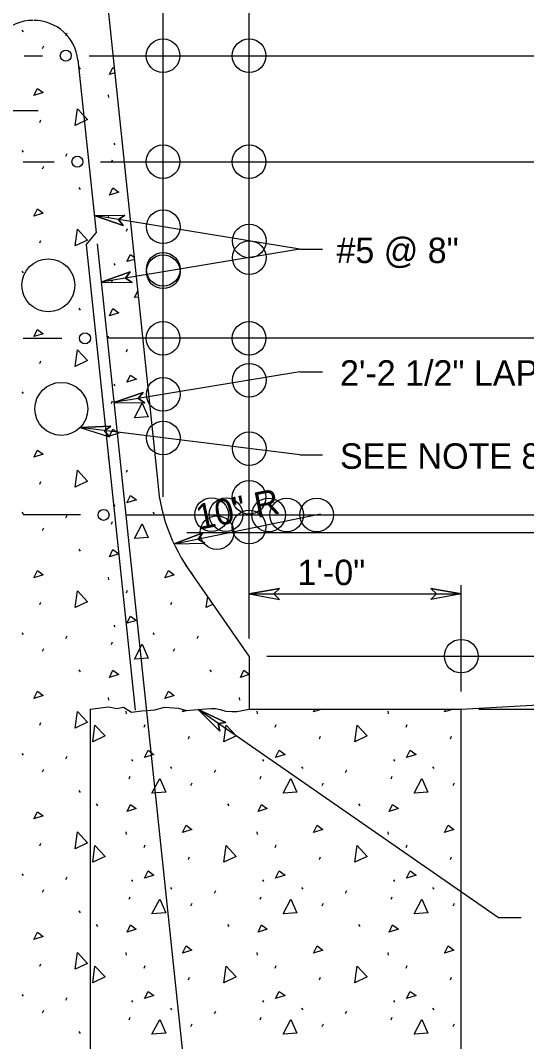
# Model space of a CAD drawing. Extents: x -26.5 to -19.2, y -3.6 to 6.6.
# Drawn here: x -23.277 to -22.083, y 2.961 to 5.371 of the extents above; entities that cross this region are included whole.
import ezdxf

# ---------------------------------------------------------------- set-up
doc = ezdxf.new("R2010")
doc.units = 0
for name, color, linetype in [('ANNO-WOUT', 7, 'Continuous'), ('CABLE_RUN', 7, 'Continuous'), ('DETL-DIMS', 7, 'Continuous'), ('DETL-PATT', 7, 'Continuous'), ('Level 10', 7, 'Continuous'), ('Level 12', 7, 'Continuous'), ('SECT-GRND_P', 7, 'Continuous'), ('SUBS-FOOT_P', 7, 'Continuous'), ('SUPR-PARA_P', 7, 'Continuous'), ('SUPR-RFRC', 7, 'Continuous')]:
    doc.layers.add(name, color=color, linetype=linetype)

msp = doc.modelspace()

# ---------------------------------------------------------------- linework, layer by layer
at = {"layer": 'ANNO-WOUT'}
for centre in [(-22.9404, 5.2872), (-22.7373, 5.2872), (-22.9404, 5.0372), (-22.7373, 5.0372), (-22.9401, 4.8836), (-22.737, 4.8501), (-22.737, 4.8109), (-22.9401, 4.7833), (-22.9401, 4.7774), (-22.9404, 4.6205), (-22.7373, 4.6205), (-22.737, 4.5216), (-22.9401, 4.4881), (-22.9401, 4.3853), (-22.737, 4.36), (-22.7373, 4.2454), (-22.826, 4.2044), (-22.7919, 4.2044), (-22.6912, 4.2039), (-22.6488, 4.2039), (-22.578, 4.2039), (-22.8133, 4.1622), (-22.7373, 4.1751), (-22.237, 3.8705)]:
    msp.add_circle(centre, 0.0397, dxfattribs=at)
at = {"layer": 'CABLE_RUN'}
for centre in [(-23.2111, 4.7455), (-23.1804, 4.4539)]:
    msp.add_circle(centre, 0.0625, dxfattribs=at)
at = {"layer": 'DETL-DIMS'}
for p, q in [((-23.1028, 4.9104), (-23.0302, 4.9113)), ((-23.1028, 4.9104), (-23.0343, 4.8864)), ((-23.0456, 4.901), (-23.0302, 4.9113)), ((-23.0343, 4.8864), (-23.0456, 4.901)), ((-23.0862, 4.7533), (-23.0177, 4.7773)), ((-23.0177, 4.7773), (-23.029, 4.7627)), ((-23.0862, 4.7533), (-23.0136, 4.7524)), ((-23.029, 4.7627), (-23.0136, 4.7524)), ((-23.0563, 4.469), (-22.9877, 4.4929)), ((-22.9877, 4.4929), (-22.999, 4.4784)), ((-23.0563, 4.469), (-22.9836, 4.4681)), ((-22.999, 4.4784), (-22.9836, 4.4681)), ((-23.1362, 4.4097), (-23.0637, 4.4133)), ((-23.1362, 4.4097), (-23.0668, 4.3883)), ((-23.0637, 4.4133), (-23.0786, 4.4025)), ((-23.0786, 4.4025), (-23.0668, 4.3883)), ((-22.9141, 4.1352), (-22.8465, 4.1617)), ((-22.8465, 4.1617), (-22.8572, 4.1468)), ((-22.8572, 4.1468), (-22.8415, 4.137)), ((-22.9141, 4.1352), (-22.8415, 4.137)), ((-22.737, 4.0173), (-22.6655, 4.0298)), ((-22.6655, 4.0298), (-22.679, 4.0173)), ((-22.237, 4.0173), (-22.3085, 4.0298)), ((-22.3085, 4.0298), (-22.295, 4.0173)), ((-22.737, 4.0173), (-22.6655, 4.0046)), ((-22.679, 4.0173), (-22.6655, 4.0046)), ((-22.237, 4.0173), (-22.3085, 4.0046)), ((-22.295, 4.0173), (-22.3085, 4.0046)), ((-22.8579, 3.7446), (-22.792, 3.7142)), ((-22.8579, 3.7446), (-22.8064, 3.6935)), ((-22.792, 3.7142), (-22.8102, 3.7116)), ((-22.8102, 3.7116), (-22.8064, 3.6935))]:
    msp.add_line(p, q, dxfattribs=at)
for points in [[(-23.0343, 4.8864), (-23.1028, 4.9104), (-23.0302, 4.9113), (-23.0456, 4.901)], [(-23.0177, 4.7773), (-23.0862, 4.7533), (-23.0136, 4.7524), (-23.029, 4.7627)], [(-22.9877, 4.4929), (-23.0563, 4.469), (-22.9836, 4.4681), (-22.999, 4.4784)], [(-23.0637, 4.4133), (-23.1362, 4.4097), (-23.0668, 4.3883), (-23.0786, 4.4025)], [(-22.8465, 4.1617), (-22.9141, 4.1352), (-22.8415, 4.137), (-22.8572, 4.1468)], [(-22.6655, 4.0298), (-22.737, 4.0173), (-22.6655, 4.0046), (-22.679, 4.0173)], [(-22.3085, 4.0298), (-22.237, 4.0173), (-22.3085, 4.0046), (-22.295, 4.0173)], [(-22.792, 3.7142), (-22.8579, 3.7446), (-22.8064, 3.6935), (-22.8102, 3.7116)]]:
    msp.add_lwpolyline(points, close=True, dxfattribs=at)
at = {"layer": 'DETL-PATT'}
for p, q in [((-23.2737, 5.3478), (-23.2707, 5.344)), ((-23.1694, 5.3347), (-23.1663, 5.3409)), ((-23.225, 5.3045), (-23.222, 5.3107)), ((-23.1393, 5.2605), (-23.1362, 5.2559)), ((-23.0545, 5.2466), (-23.0666, 5.2427)), ((-23.0697, 5.1948), (-23.0689, 5.1886)), ((-23.2312, 5.1299), (-23.2289, 5.136)), ((-23.2737, 5.0634), (-23.2707, 5.0595)), ((-23.0565, 5.0812), (-23.0542, 5.0773)), ((-23.1694, 5.0502), (-23.1663, 5.0564)), ((-23.062, 5.0356), (-23.0596, 5.0417)), ((-23.225, 5.0201), (-23.222, 5.0263)), ((-23.1393, 4.976), (-23.1362, 4.9714)), ((-23.0697, 4.9103), (-23.0689, 4.9042)), ((-23.0264, 4.8732), (-23.0241, 4.8794)), ((-23.2312, 4.8454), (-23.2289, 4.8516)), ((-23.0565, 4.7967), (-23.0542, 4.7929)), ((-23.0081, 4.8068), (-23.0256, 4.8014)), ((-23.2737, 4.7789), (-23.2707, 4.7751)), ((-23.062, 4.7511), (-23.0596, 4.7573)), ((-23.0079, 4.7171), (-23.0002, 4.7316)), ((-22.9987, 4.7178), (-23.0079, 4.7171)), ((-23.1393, 4.6916), (-23.1362, 4.687)), ((-23.0697, 4.6259), (-23.0689, 4.6197)), ((-23.0264, 4.5888), (-23.0241, 4.595)), ((-23.2312, 4.561), (-23.2289, 4.5672)), ((-23.0565, 4.5123), (-23.0542, 4.5084)), ((-23.2737, 4.4945), (-23.2707, 4.4906)), ((-23.062, 4.4667), (-23.0596, 4.4729)), ((-23.0697, 4.3415), (-23.0689, 4.3353)), ((-23.0264, 4.3044), (-23.0241, 4.3105)), ((-23.2312, 4.2765), (-23.2289, 4.2827)), ((-23.0565, 4.2278), (-23.0542, 4.224)), ((-23.2737, 4.2101), (-23.2707, 4.2062)), ((-23.1694, 4.1969), (-23.1663, 4.2031)), ((-22.9646, 4.2101), (-22.9615, 4.2062)), ((-23.225, 4.1668), (-23.222, 4.173)), ((-23.062, 4.1822), (-23.0596, 4.1884)), ((-23.1393, 4.1227), (-23.1362, 4.1181)), ((-23.0697, 4.057), (-23.0689, 4.0508)), ((-23.0264, 4.0199), (-23.0241, 4.0261)), ((-22.8386, 3.9851), (-22.835, 4.0113)), ((-23.2312, 3.9921), (-23.2289, 3.9983)), ((-22.9221, 3.9921), (-22.9197, 3.9983)), ((-22.8222, 3.9929), (-22.8386, 3.9851)), ((-23.0565, 3.9434), (-23.0542, 3.9395)), ((-23.2737, 3.9256), (-23.2707, 3.9218)), ((-23.1694, 3.9125), (-23.1663, 3.9187)), ((-23.062, 3.8978), (-23.0596, 3.904)), ((-22.9646, 3.9256), (-22.9615, 3.9218)), ((-22.8602, 3.9125), (-22.8571, 3.9187)), ((-23.225, 3.8823), (-23.222, 3.8885)), ((-22.9159, 3.8823), (-22.9128, 3.8885)), ((-23.1393, 3.8383), (-23.1362, 3.8336)), ((-22.8301, 3.8383), (-22.827, 3.8336)), ((-22.737, 3.8271), (-22.7574, 3.8205)), ((-23.0697, 3.7726), (-23.0689, 3.7664)), ((-22.7605, 3.7726), (-22.7597, 3.7664)), ((-23.0283, 3.7404), (-23.0275, 3.7342)), ((-22.8946, 3.7389), (-22.8919, 3.7442)), ((-22.8837, 3.7424), (-22.8946, 3.7389)), ((-22.7191, 3.7404), (-22.7184, 3.7342)), ((-22.5854, 3.7389), (-22.5821, 3.7455)), ((-22.5647, 3.7455), (-22.5854, 3.7389)), ((-22.41, 3.7404), (-22.4092, 3.7342)), ((-22.2762, 3.7389), (-22.2729, 3.7455)), ((-22.2555, 3.7455), (-22.2762, 3.7389)), ((-23.2312, 3.7077), (-23.2289, 3.7138)), ((-22.985, 3.7033), (-22.9827, 3.7095)), ((-22.6758, 3.7033), (-22.6735, 3.7095)), ((-22.3667, 3.7033), (-22.3644, 3.7095)), ((-22.8807, 3.6755), (-22.8784, 3.6817)), ((-22.5715, 3.6755), (-22.5692, 3.6817)), ((-22.2623, 3.6755), (-22.26, 3.6817)), ((-23.2737, 3.6412), (-23.2707, 3.6373)), ((-23.1694, 3.628), (-23.1663, 3.6342)), ((-23.0152, 3.6268), (-23.0128, 3.6229)), ((-22.706, 3.6268), (-22.7037, 3.6229)), ((-22.3968, 3.6268), (-22.3945, 3.6229)), ((-23.225, 3.5979), (-23.222, 3.6041)), ((-22.9232, 3.609), (-22.9201, 3.6052)), ((-22.8188, 3.5959), (-22.8157, 3.6021)), ((-22.614, 3.609), (-22.6109, 3.6052)), ((-22.5097, 3.5959), (-22.5066, 3.6021)), ((-22.3048, 3.609), (-22.3017, 3.6052)), ((-23.0206, 3.5812), (-23.0183, 3.5874)), ((-22.8745, 3.5657), (-22.8714, 3.5719)), ((-22.7114, 3.5812), (-22.7091, 3.5874)), ((-22.5653, 3.5657), (-22.5622, 3.5719)), ((-22.4022, 3.5812), (-22.3999, 3.5874)), ((-22.2561, 3.5657), (-22.253, 3.5719)), ((-23.1393, 3.5538), (-23.1362, 3.5492)), ((-23.0979, 3.5217), (-23.0948, 3.517)), ((-22.7887, 3.5217), (-22.7856, 3.517)), ((-22.4795, 3.5217), (-22.4764, 3.517)), ((-23.0283, 3.456), (-23.0275, 3.4498)), ((-22.7191, 3.456), (-22.7184, 3.4498)), ((-22.41, 3.456), (-22.4092, 3.4498)), ((-23.2312, 3.4232), (-23.2289, 3.4294)), ((-22.985, 3.4189), (-22.9827, 3.4251)), ((-22.6758, 3.4189), (-22.6735, 3.4251)), ((-22.3667, 3.4189), (-22.3644, 3.4251)), ((-22.8807, 3.3911), (-22.8784, 3.3972)), ((-22.5715, 3.3911), (-22.5692, 3.3972)), ((-22.2623, 3.3911), (-22.26, 3.3972)), ((-23.2737, 3.3567), (-23.2707, 3.3529)), ((-23.1694, 3.3436), (-23.1663, 3.3498)), ((-23.0152, 3.3424), (-23.0128, 3.3385)), ((-22.706, 3.3424), (-22.7037, 3.3385)), ((-22.3968, 3.3424), (-22.3945, 3.3385)), ((-23.225, 3.3135), (-23.222, 3.3196)), ((-23.0206, 3.2968), (-23.0183, 3.3029)), ((-22.9232, 3.3246), (-22.9201, 3.3207)), ((-22.8188, 3.3114), (-22.8157, 3.3176)), ((-22.7114, 3.2968), (-22.7091, 3.3029)), ((-22.614, 3.3246), (-22.6109, 3.3207)), ((-22.5097, 3.3114), (-22.5066, 3.3176)), ((-22.4022, 3.2968), (-22.3999, 3.3029)), ((-22.3048, 3.3246), (-22.3017, 3.3207)), ((-22.8745, 3.2813), (-22.8714, 3.2875)), ((-22.5653, 3.2813), (-22.5622, 3.2875)), ((-22.2561, 3.2813), (-22.253, 3.2875)), ((-23.1393, 3.2694), (-23.1362, 3.2648)), ((-23.0979, 3.2372), (-23.0948, 3.2326)), ((-22.7887, 3.2372), (-22.7856, 3.2326)), ((-22.4795, 3.2372), (-22.4764, 3.2326)), ((-23.0283, 3.1715), (-23.0275, 3.1654)), ((-22.7191, 3.1715), (-22.7184, 3.1654)), ((-22.41, 3.1715), (-22.4092, 3.1654)), ((-23.2312, 3.1388), (-23.2289, 3.1449)), ((-22.985, 3.1344), (-22.9827, 3.1406)), ((-22.6758, 3.1344), (-22.6735, 3.1406)), ((-22.3667, 3.1344), (-22.3644, 3.1406)), ((-22.8807, 3.1066), (-22.8784, 3.1128)), ((-22.5715, 3.1066), (-22.5692, 3.1128)), ((-22.2623, 3.1066), (-22.26, 3.1128)), ((-23.2737, 3.0723), (-23.2707, 3.0684)), ((-23.1694, 3.0592), (-23.1663, 3.0653)), ((-23.0152, 3.0579), (-23.0128, 3.0541)), ((-22.9232, 3.0401), (-22.9201, 3.0363)), ((-22.706, 3.0579), (-22.7037, 3.0541)), ((-22.614, 3.0401), (-22.6109, 3.0363)), ((-22.3968, 3.0579), (-22.3945, 3.0541)), ((-22.3048, 3.0401), (-22.3017, 3.0363)), ((-23.225, 3.029), (-23.222, 3.0352)), ((-23.0206, 3.0123), (-23.0183, 3.0185)), ((-22.8188, 3.027), (-22.8157, 3.0332)), ((-22.7114, 3.0123), (-22.7091, 3.0185)), ((-22.5097, 3.027), (-22.5066, 3.0332)), ((-22.4022, 3.0123), (-22.3999, 3.0185)), ((-22.8745, 2.9969), (-22.8714, 3.003)), ((-22.5653, 2.9969), (-22.5622, 3.003)), ((-22.2561, 2.9969), (-22.253, 3.003)), ((-23.1393, 2.985), (-23.1362, 2.9803))]:
    msp.add_line(p, q, dxfattribs=at)
for points in [[(-23.0666, 5.2427), (-23.0589, 5.2597), (-23.0556, 5.2574)], [(-23.2451, 5.1932), (-23.2366, 5.2102), (-23.2235, 5.2002), (-23.2451, 5.1932)], [(-23.1478, 5.1229), (-23.1423, 5.1623), (-23.1184, 5.1368), (-23.1478, 5.1229)], [(-23.0666, 4.9583), (-23.0589, 4.9753), (-23.045, 4.9652), (-23.0666, 4.9583)], [(-23.2451, 4.9088), (-23.2366, 4.9258), (-23.2235, 4.9158), (-23.2451, 4.9088)], [(-23.1478, 4.8385), (-23.1423, 4.8779), (-23.1184, 4.8524), (-23.1478, 4.8385)], [(-23.0256, 4.8014), (-23.0171, 4.8184), (-23.0087, 4.8123)], [(-23.0666, 4.6738), (-23.0589, 4.6908), (-23.045, 4.6808), (-23.0666, 4.6738)], [(-23.2451, 4.6244), (-23.2366, 4.6414), (-23.2235, 4.6313), (-23.2451, 4.6244)], [(-23.1478, 4.554), (-23.1423, 4.5934), (-23.1184, 4.5679), (-23.1478, 4.554)], [(-23.0256, 4.5169), (-23.0171, 4.5339), (-23.0032, 4.5239), (-23.0256, 4.5169)], [(-23.0079, 4.4327), (-22.9893, 4.4675), (-22.9754, 4.435), (-23.0079, 4.4327)], [(-23.0666, 4.3894), (-23.0589, 4.4064), (-23.045, 4.3963), (-23.0666, 4.3894)], [(-23.2451, 4.3399), (-23.2366, 4.3569), (-23.2235, 4.3469), (-23.2451, 4.3399)], [(-23.1478, 4.2696), (-23.1423, 4.309), (-23.1184, 4.2835), (-23.1478, 4.2696)], [(-23.0256, 4.2325), (-23.0171, 4.2495), (-23.0032, 4.2394), (-23.0256, 4.2325)], [(-23.0079, 4.1482), (-22.9893, 4.183), (-22.9754, 4.1505), (-23.0079, 4.1482)], [(-23.0666, 4.1049), (-23.0589, 4.1219), (-23.045, 4.1119), (-23.0666, 4.1049)], [(-23.2451, 4.0555), (-23.2366, 4.0725), (-23.2235, 4.0624), (-23.2451, 4.0555)], [(-22.936, 4.0555), (-22.9275, 4.0725), (-22.9143, 4.0624), (-22.936, 4.0555)], [(-23.1478, 3.9851), (-23.1423, 4.0246), (-23.1184, 3.999), (-23.1478, 3.9851)], [(-23.0256, 3.948), (-23.0171, 3.965), (-23.0032, 3.955), (-23.0256, 3.948)], [(-23.0079, 3.8638), (-22.9893, 3.8986), (-22.9754, 3.8661), (-23.0079, 3.8638)], [(-23.0666, 3.8205), (-23.0589, 3.8375), (-23.045, 3.8275), (-23.0666, 3.8205)], [(-22.7574, 3.8205), (-22.7497, 3.8375), (-22.737, 3.8283)], [(-23.2451, 3.771), (-23.2366, 3.788), (-23.2235, 3.778), (-23.2451, 3.771)], [(-22.936, 3.771), (-22.9275, 3.788), (-22.9143, 3.778), (-22.936, 3.771)], [(-23.1478, 3.7007), (-23.1423, 3.7401), (-23.1184, 3.7146), (-23.1478, 3.7007)], [(-23.1064, 3.6685), (-23.101, 3.708), (-23.077, 3.6825), (-23.1064, 3.6685)], [(-22.7972, 3.6685), (-22.7918, 3.708), (-22.7678, 3.6825), (-22.7972, 3.6685)], [(-22.488, 3.6685), (-22.4826, 3.708), (-22.4586, 3.6825), (-22.488, 3.6685)], [(-22.9842, 3.6314), (-22.9757, 3.6484), (-22.9618, 3.6384), (-22.9842, 3.6314)], [(-22.6751, 3.6314), (-22.6666, 3.6484), (-22.6527, 3.6384), (-22.6751, 3.6314)], [(-22.3659, 3.6314), (-22.3574, 3.6484), (-22.3435, 3.6384), (-22.3659, 3.6314)], [(-22.9665, 3.5472), (-22.9479, 3.582), (-22.934, 3.5495), (-22.9665, 3.5472)], [(-22.6573, 3.5472), (-22.6387, 3.582), (-22.6248, 3.5495), (-22.6573, 3.5472)], [(-22.3481, 3.5472), (-22.3296, 3.582), (-22.3157, 3.5495), (-22.3481, 3.5472)], [(-23.0252, 3.5039), (-23.0175, 3.5209), (-23.0036, 3.5109), (-23.0252, 3.5039)], [(-22.716, 3.5039), (-22.7083, 3.5209), (-22.6944, 3.5109), (-22.716, 3.5039)], [(-22.4069, 3.5039), (-22.3991, 3.5209), (-22.3852, 3.5109), (-22.4069, 3.5039)], [(-23.2451, 3.4866), (-23.2366, 3.5036), (-23.2235, 3.4935), (-23.2451, 3.4866)], [(-22.8946, 3.4544), (-22.8861, 3.4714), (-22.8729, 3.4614), (-22.8946, 3.4544)], [(-22.5854, 3.4544), (-22.5769, 3.4714), (-22.5638, 3.4614), (-22.5854, 3.4544)], [(-22.2762, 3.4544), (-22.2677, 3.4714), (-22.2546, 3.4614), (-22.2762, 3.4544)], [(-23.1478, 3.4163), (-23.1423, 3.4557), (-23.1184, 3.4302), (-23.1478, 3.4163)], [(-23.1064, 3.3841), (-23.101, 3.4235), (-23.077, 3.398), (-23.1064, 3.3841)], [(-22.7972, 3.3841), (-22.7918, 3.4235), (-22.7678, 3.398), (-22.7972, 3.3841)], [(-22.488, 3.3841), (-22.4826, 3.4235), (-22.4586, 3.398), (-22.488, 3.3841)], [(-22.9842, 3.347), (-22.9757, 3.364), (-22.9618, 3.354), (-22.9842, 3.347)], [(-22.6751, 3.347), (-22.6666, 3.364), (-22.6527, 3.354), (-22.6751, 3.347)], [(-22.3659, 3.347), (-22.3574, 3.364), (-22.3435, 3.354), (-22.3659, 3.347)], [(-22.9665, 3.2628), (-22.9479, 3.2975), (-22.934, 3.2651), (-22.9665, 3.2628)], [(-22.6573, 3.2628), (-22.6387, 3.2975), (-22.6248, 3.2651), (-22.6573, 3.2628)], [(-22.3481, 3.2628), (-22.3296, 3.2975), (-22.3157, 3.2651), (-22.3481, 3.2628)], [(-23.0252, 3.2195), (-23.0175, 3.2365), (-23.0036, 3.2264), (-23.0252, 3.2195)], [(-22.716, 3.2195), (-22.7083, 3.2365), (-22.6944, 3.2264), (-22.716, 3.2195)], [(-22.4069, 3.2195), (-22.3991, 3.2365), (-22.3852, 3.2264), (-22.4069, 3.2195)], [(-23.2451, 3.2021), (-23.2366, 3.2192), (-23.2235, 3.2091), (-23.2451, 3.2021)], [(-22.8946, 3.17), (-22.8861, 3.187), (-22.8729, 3.177), (-22.8946, 3.17)], [(-22.5854, 3.17), (-22.5769, 3.187), (-22.5638, 3.177), (-22.5854, 3.17)], [(-22.2762, 3.17), (-22.2677, 3.187), (-22.2546, 3.177), (-22.2762, 3.17)], [(-23.1478, 3.1318), (-23.1423, 3.1712), (-23.1184, 3.1457), (-23.1478, 3.1318)], [(-23.1064, 3.0997), (-23.101, 3.1391), (-23.077, 3.1136), (-23.1064, 3.0997)], [(-22.7972, 3.0997), (-22.7918, 3.1391), (-22.7678, 3.1136), (-22.7972, 3.0997)], [(-22.488, 3.0997), (-22.4826, 3.1391), (-22.4586, 3.1136), (-22.488, 3.0997)], [(-22.9842, 3.0626), (-22.9757, 3.0796), (-22.9618, 3.0695), (-22.9842, 3.0626)], [(-22.6751, 3.0626), (-22.6666, 3.0796), (-22.6527, 3.0695), (-22.6751, 3.0626)], [(-22.3659, 3.0626), (-22.3574, 3.0796), (-22.3435, 3.0695), (-22.3659, 3.0626)], [(-22.9665, 2.9783), (-22.9479, 3.0131), (-22.934, 2.9806), (-22.9665, 2.9783)], [(-22.6573, 2.9783), (-22.6387, 3.0131), (-22.6248, 2.9806), (-22.6573, 2.9783)], [(-22.3481, 2.9783), (-22.3296, 3.0131), (-22.3157, 2.9806), (-22.3481, 2.9783)]]:
    msp.add_lwpolyline(points, dxfattribs=at)
at = {"layer": 'Level 10'}
for p, q in [((-22.737, 3.9121), (-22.737, 6.5163)), ((-22.9401, 4.2462), (-22.9401, 6.0163)), ((-23.268, 5.2872), (-23.2245, 5.2872)), ((-23.1151, 5.2872), (-20.9662, 5.2872)), ((-23.2352, 5.1576), (-23.3516, 5.1576)), ((-23.2708, 5.0372), (-23.1971, 5.0372)), ((-23.0877, 5.0372), (-20.9662, 5.0372)), ((-22.6179, 4.8305), (-23.1028, 4.9104)), ((-22.6179, 4.8305), (-23.0862, 4.7533)), ((-22.6179, 4.8305), (-22.564, 4.8305)), ((-23.2708, 4.6205), (-23.1792, 4.6205)), ((-20.9662, 4.6205), (-23.0698, 4.6205)), ((-22.6179, 4.5412), (-23.0563, 4.469)), ((-22.6179, 4.5412), (-22.564, 4.5412)), ((-22.6179, 4.3452), (-23.1362, 4.4097)), ((-22.6179, 4.3452), (-22.564, 4.3452)), ((-23.1354, 4.2039), (-23.2708, 4.2039)), ((-23.026, 4.2039), (-20.9662, 4.2039)), ((-22.5689, 4.2057), (-22.9145, 4.1351)), ((-22.8845, 4.1622), (-20.7162, 4.1622)), ((-22.237, 3.7872), (-22.237, 4.0381)), ((-22.737, 4.0173), (-22.237, 4.0173)), ((-22.6954, 3.8705), (-20.7162, 3.8705)), ((-22.149, 3.2534), (-22.8579, 3.7446)), ((-22.1953, 3.7455), (-20.4662, 3.7455)), ((-22.0952, 3.2534), (-22.149, 3.2534))]:
    msp.add_line(p, q, dxfattribs=at)
at = {"layer": 'SECT-GRND_P'}
msp.add_line((-22.237, 3.7455), (-21.237, 3.8014), dxfattribs=at)
at = {"layer": 'SUBS-FOOT_P'}
for p, q in [((-23.112, 3.7455), (-23.112, 1.7455)), ((-22.737, 3.7455), (-22.237, 3.7455)), ((-22.237, 1.7455), (-22.237, 3.7455))]:
    msp.add_line(p, q, dxfattribs=at)
msp.add_lwpolyline([(-23.112, 3.7455), (-23.0688, 3.751), (-23.0497, 3.7474), (-23.0337, 3.7498), (-23.015, 3.7383), (-22.9903, 3.7412), (-22.9596, 3.7439), (-22.937, 3.7505), (-22.9043, 3.7475), (-22.8847, 3.7423), (-22.8492, 3.7454), (-22.8389, 3.7463), (-22.8268, 3.7467), (-22.8165, 3.7467), (-22.8054, 3.7445), (-22.7928, 3.7409), (-22.7785, 3.7396), (-22.766, 3.7396), (-22.737, 3.7455)], dxfattribs=at)
at = {"layer": 'SUPR-PARA_P'}
for p, q in [((-23.0778, 5.4676), (-22.954, 4.2941)), ((-22.737, 3.8705), (-22.8874, 4.0865)), ((-22.737, 3.8705), (-22.737, 3.7455))]:
    msp.add_line(p, q, dxfattribs=at)
msp.add_arc((-22.5378, 4.3132), 0.4167, 182.6318, 216.7526, dxfattribs=at)
at = {"layer": 'SUPR-RFRC'}
for p, q in [((-23.1415, 5.2773), (-23.0985, 4.8695)), ((-23.1217, 4.8409), (-23.0985, 4.8695)), ((-23.0958, 4.8436), (-22.6767, 0.8705)), ((-23.1217, 4.8409), (-23.0059, 3.7428))]:
    msp.add_line(p, q, dxfattribs=at)
for centre in [(-23.1698, 5.2872), (-23.1424, 5.0372), (-23.1245, 4.6205), (-23.0807, 4.2039)]:
    msp.add_circle(centre, 0.013, dxfattribs=at)
for centre, start, end in [((-23.2474, 5.2664), 90, 180), ((-23.2451, 5.2664), 6.0207, 90)]:
    msp.add_arc(centre, 0.1042, start, end, dxfattribs=at)

# ---------------------------------------------------------------- texts
at = {"layer": 'Level 12'}
for s, p in [('#5 @ 8"', (-22.5313, 4.798)), ('2\'-2 1/2" LAP (TYP.)', (-22.5229, 4.5087)), ('SEE NOTE 8 (TYP.)', (-22.5229, 4.3127)), ('1\'-0"', (-22.6231, 4.0381))]:
    msp.add_text(s, height=0.06001, dxfattribs=at).set_placement(p)
msp.add_text('10" R', height=0.06001, rotation=11.5385, dxfattribs=at).set_placement((-22.8559, 4.1683))

doc.saveas('drawing.dxf')
